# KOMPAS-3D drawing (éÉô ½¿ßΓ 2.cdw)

Referenced files: общ.cdw
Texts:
  Электроснабжение первой детской клинической больницы  по адресу: г. Иваново, ул. Мальцева д.3 (Главный корпус)
  Microsoft
  Текст на чертеже
  Размерные надписи
  Шероховатость
  Линия-выноска #1
  Линия-выноска #2
  Линия-выноска #3
  Отклонения формы и база
  Заголовок таблицы
  Ячейка таблицы
  Стрелка вида
  Обозначение изменения
  Фигурная скобка
  Номер узла
  Марка координационной оси
  VRCB
  Выносная надпись
  Обозначение узла
  Марка/позиционное обозначение с линией-выноской
  Марка/позиционное обозначение на линии
  Марка/позиционное обозначение без линии-выноски
  Номер группы
  Р кВт
  Ток, А
  Гр1
  Гр2
  Гр3
  Гр4
  ВА 47-29 (3)
  Щиток РЩ1
  ВРУ (ЩМП-7)
  Гр5
  Гр6
  Гр7
  Гр8
  Щиток РЩ2
  Щиток РЩ3
  Щиток РЩ4
  Щиток РЩ5
  Щиток РЩ6
  Щиток РЩ7
  Гр9
  Щиток РЩ8
  Щиток РЩ9
  ВВГнгLS 5х10 мм2 скрыто
  в гофр. ПВХ трубе
  CONTINUOUS0
  Электроснабжение первой детской клинической больницы
  по адресу: г. Иваново, ул. Мальцева д.3 (Главный корпус)
  ГИП
  Разработ
  Однолинейная схема ВРУ (лист 2)
  Кочетков
  ООО "Мастер Лайт"
Dimensions and other numbers on the sheet: 2012-0011-ЭС; 7; 13.22; 20.2; 5.0; 7.9; 40А; 16А; 4; 1:1; 5; 0; 1; 2; 3; 6; 8; 9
